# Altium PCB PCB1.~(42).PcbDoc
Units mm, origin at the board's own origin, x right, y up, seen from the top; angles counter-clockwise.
Board outline 145.29 x 144.91 mm, 2 copper layers (Top Layer, Bottom Layer); 41 components, 36 nets, 219 pads, 0 vias.
Unrouted connection lines stored in the file: 1.
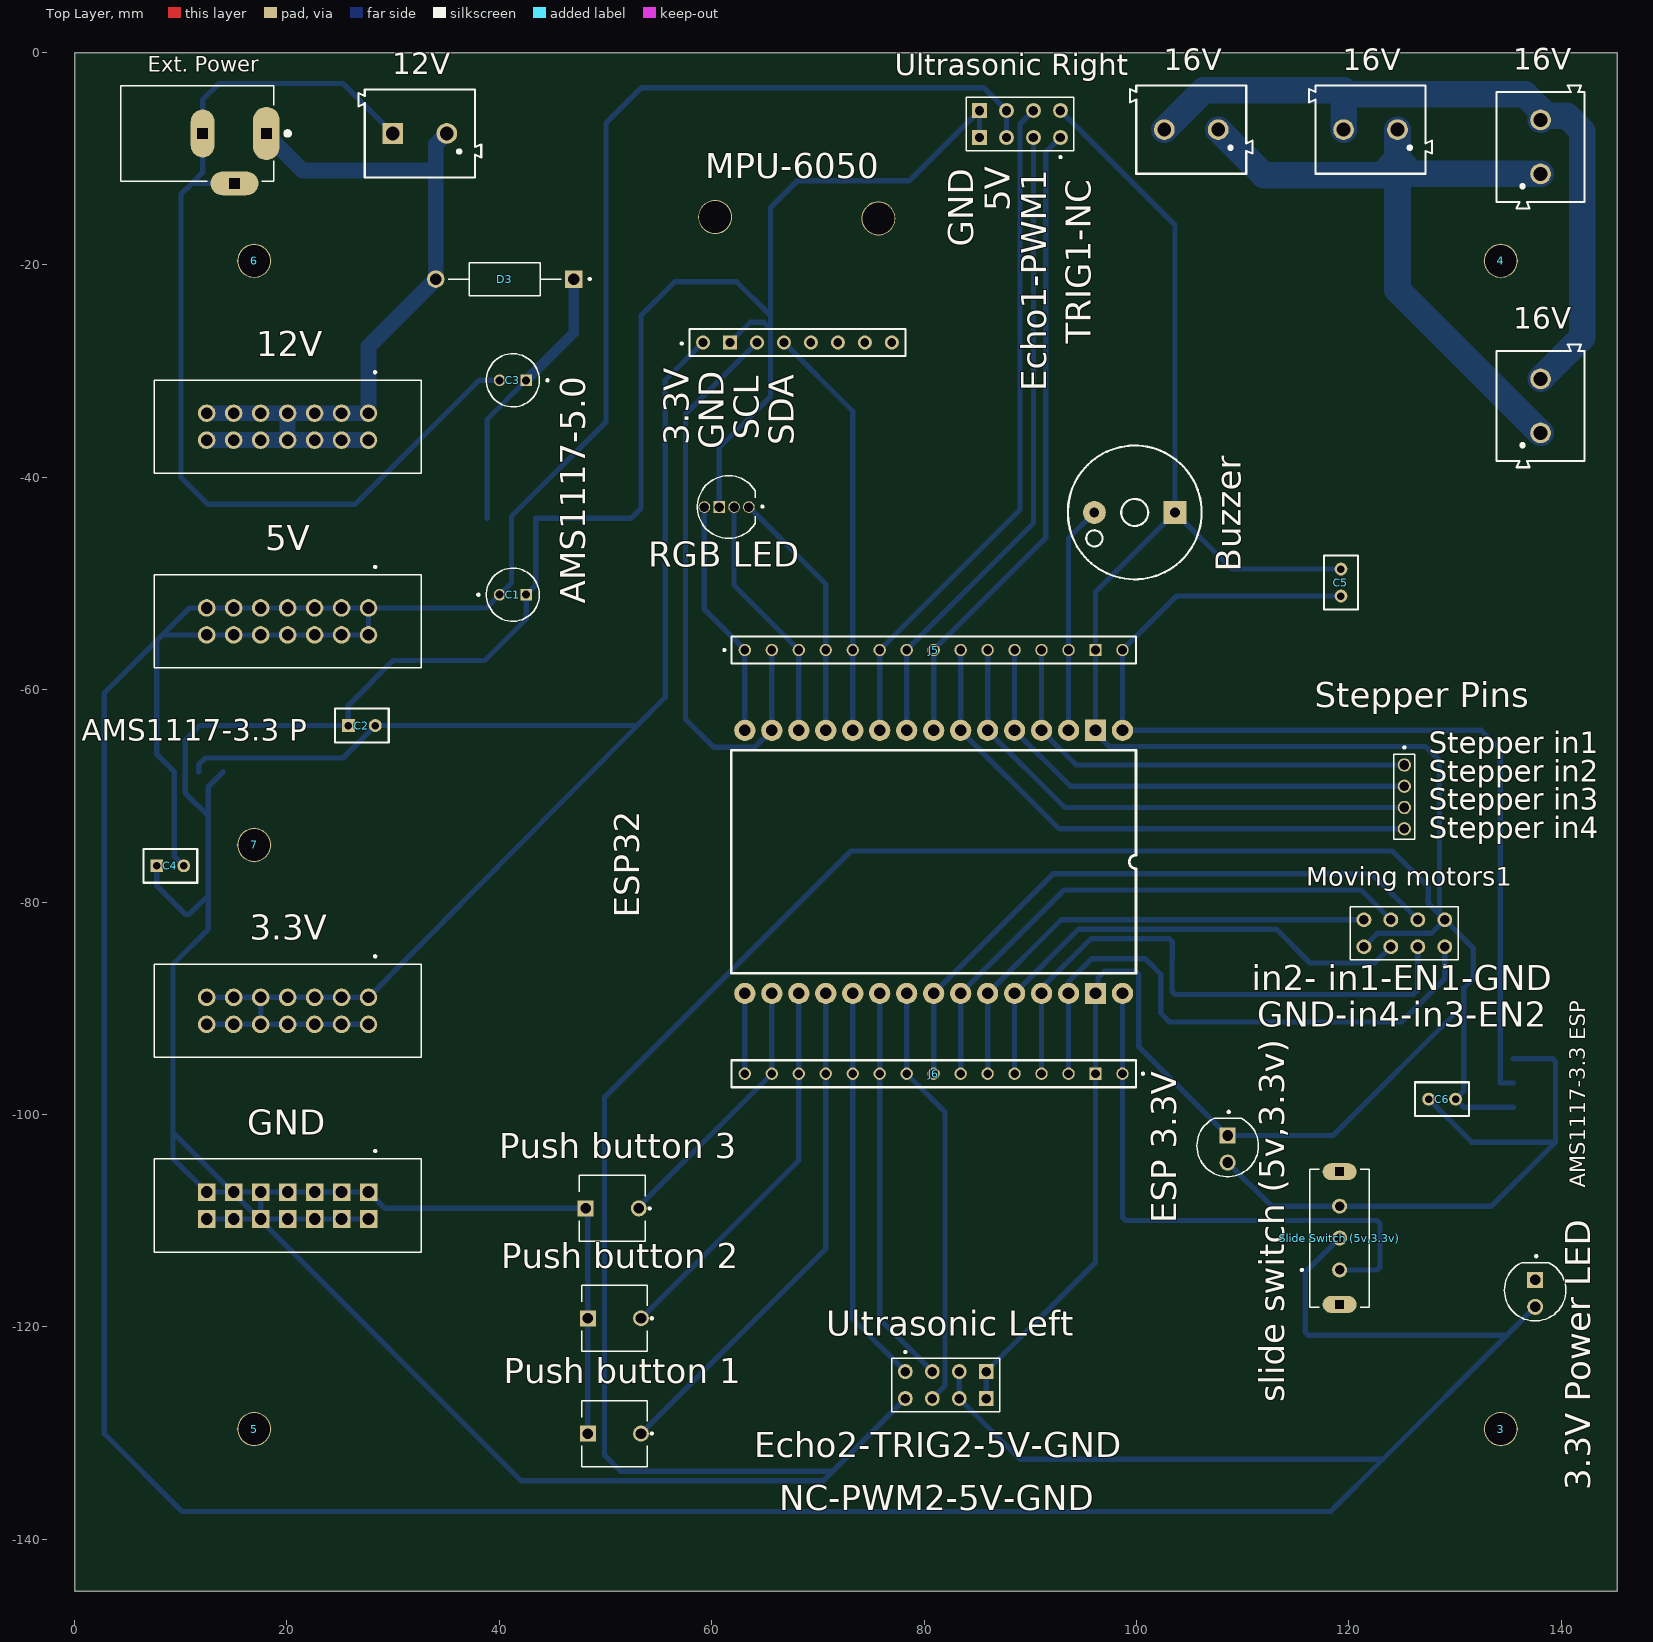
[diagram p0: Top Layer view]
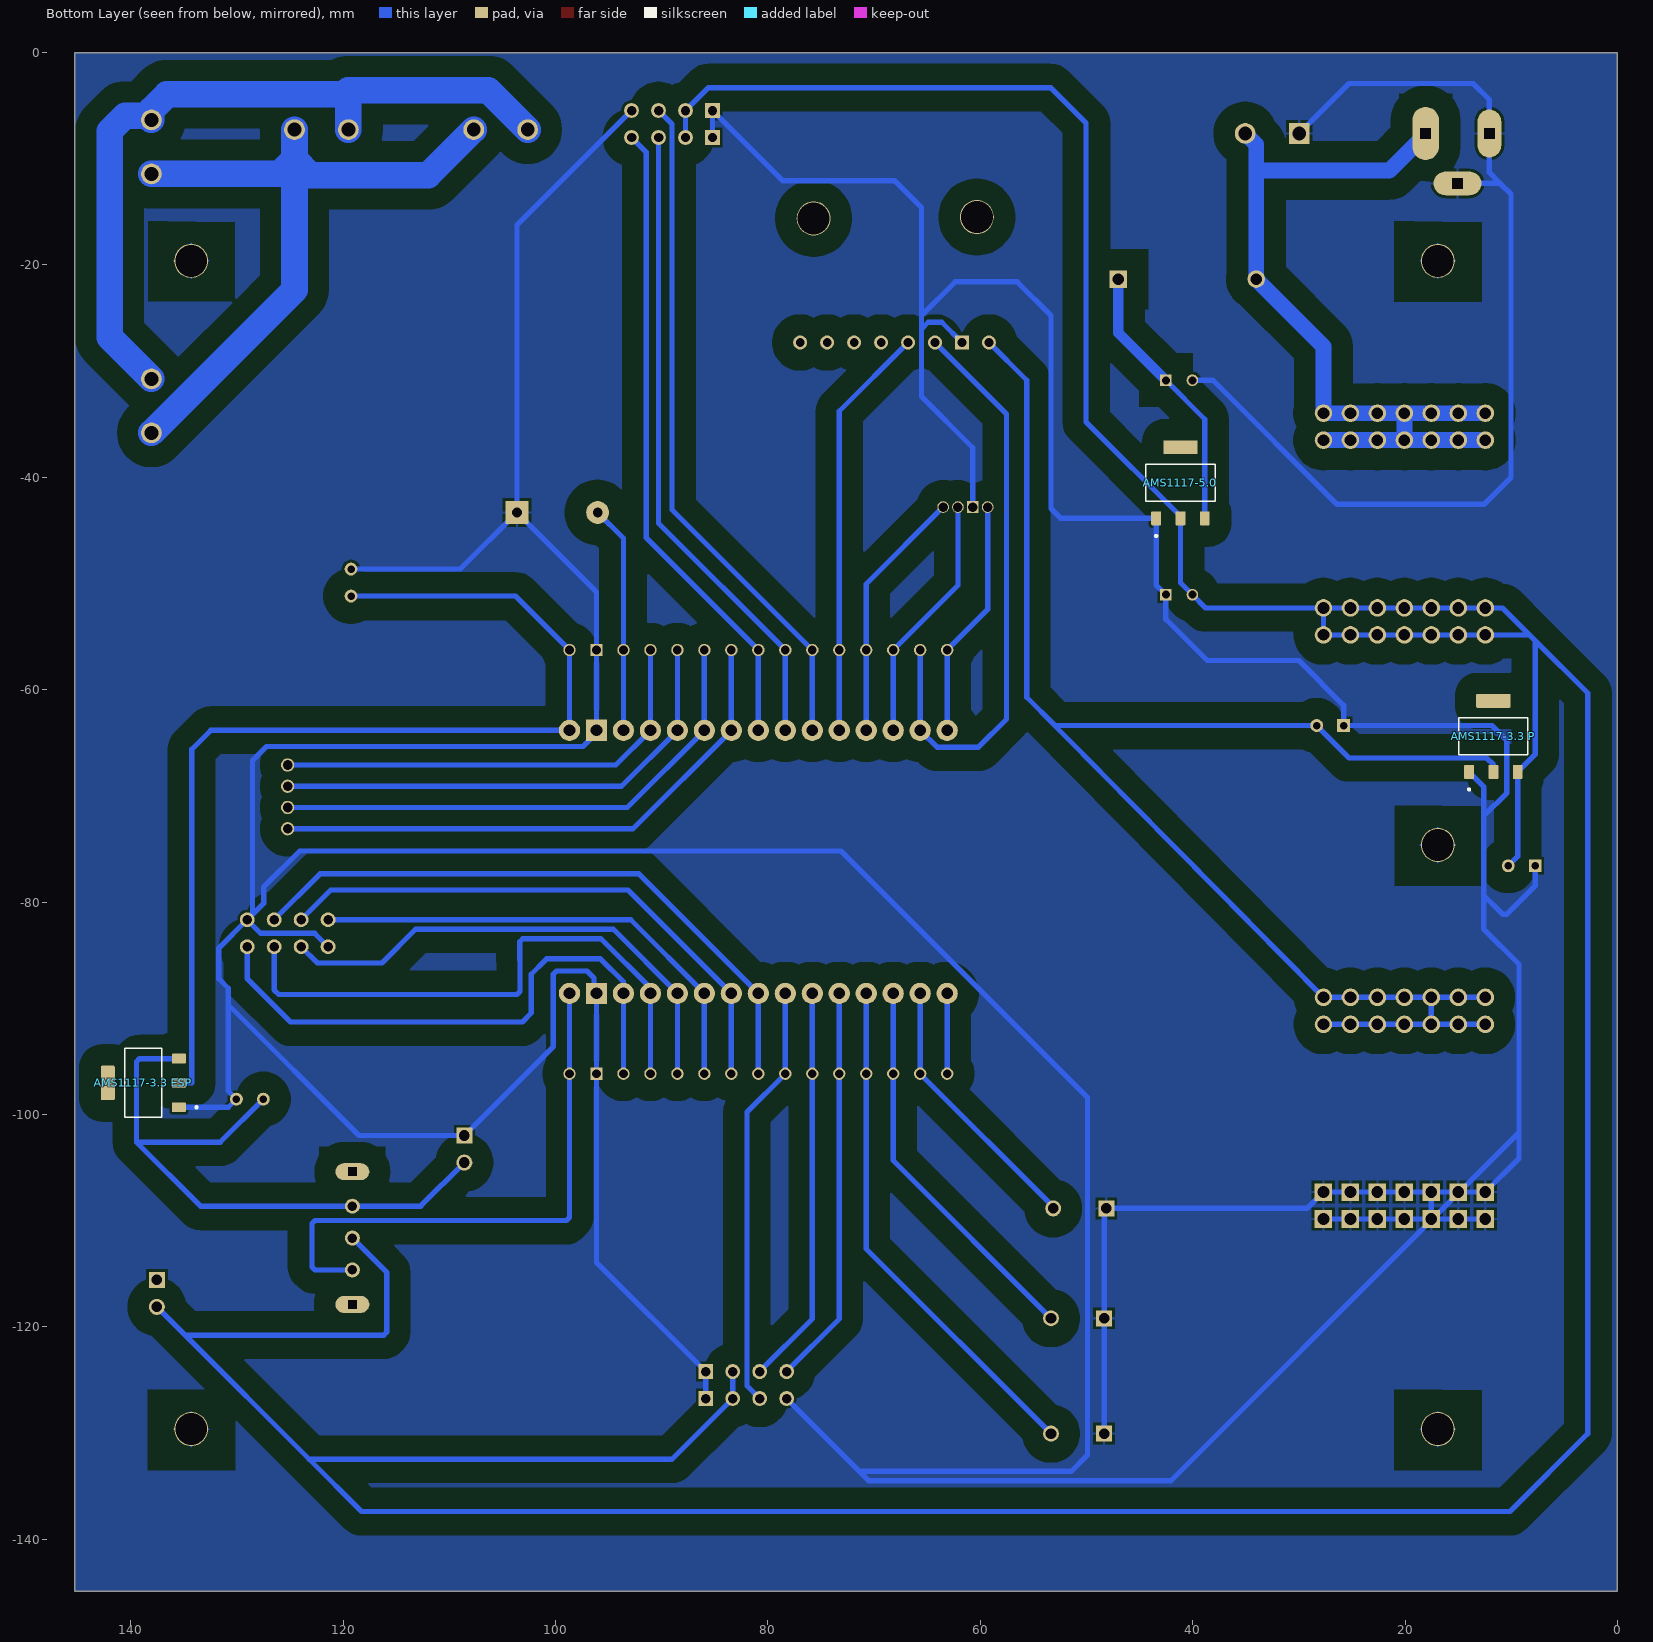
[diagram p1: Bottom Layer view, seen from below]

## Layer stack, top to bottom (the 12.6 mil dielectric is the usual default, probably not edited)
Top Solder: solder mask 0.0102, Solder Resist, Dk 3.5
Top Layer: signal copper 0.0356
Dielectric 1: dielectric 0.32, FR-4, Dk 4.8
Bottom Layer: signal copper 0.0356
Bottom Solder: solder mask 0.0102, Solder Resist, Dk 3.5

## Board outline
0,-144.907 145.288,-144.907 145.288,0 0,0

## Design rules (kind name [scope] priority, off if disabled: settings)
Clearance [All] p1: gap=0.254 ignorepadtopadclearanceinfootprint=FALSE except(0: Arc-Hole Track-Hole SMDPad-Hole THPad-Hole Via-Hole Fill-Hole Poly-Hole Region-Hole Text-Hole; 2: Arc-Poly Track-Poly SMDPad-Poly THPad-Poly)
PolygonConnect [All] p1: connectstyle=Relief reliefconductorwidth=0.254 reliefentries=4 polygonreliefangle="90 Angle" airgapwidth=0.254
RoutingLayers [All] p1: top layer_v5=FALSE bottom layer_v5=TRUE
RoutingVias [All] p1: holewidth=0.711 width=1.27 viastyle="Through Hole" minholewidth=0.711 minwidth=1.27 maxholewidth=0.711 maxwidth=1.27
SolderMaskExpansion [All] p1: expansion=0.102 istentingtop=FALSE
Width [All] p1: maxlimit=2.5 minlimit=0.254 preferedwidth=0.5
29 further rules are at their usual default settings.

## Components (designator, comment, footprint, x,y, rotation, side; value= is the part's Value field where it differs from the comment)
3 "Mounting Hole" PCBComponent_1 134.304,-129.619 r90 top
3.3V "3.3v pin headers block" AMPHENOL_52601-S14-4LF#1 20.066,-90.235 r180 top
"3.3V Power LED" "LED 5mm" "LED 5mm" 137.541,-116.84 r270 top
4 "Mounting Hole" PCBComponent_1 134.304,-19.619 r90 top
5 "Mounting Hole" PCBComponent_1 16.916,-129.619 r90 top
5V "5v pin headers block" AMPHENOL_52601-S14-4LF#1 20.066,-53.568 r180 top
6 "Mounting Hole" PCBComponent_1 16.916,-19.619 r90 top
7 "Mounting Hole" PCBComponent_1 16.916,-74.619 r90 top
12V "12v pin headers block" AMPHENOL_52601-S14-4LF#1 20.066,-35.235 r180 top
12V "From Buck" 691213510002#1 32.512,-7.62 r180 top
16V "From Buck" 691213510002#2 138.049,-8.89 r90 top
16V "From Buck" 691213510002#2 138.049,-33.274 r90 top
16V "From Buck" 691213510002#2 122.036,-7.26 r180 top
16V "From Buck" 691213510002#2 105.156,-7.26 r180 top
"AMS1117-3.3 ESP" "AMS1117-3.3" SOT229P700X180-4N 138.811,-97.028 r0 bottom
"AMS1117-3.3 P" "AMS1117-3.3" SOT229P700X180-4N 11.684,-64.389 r90 bottom
AMS1117-5.0 "AMS1117-5.0" SOT229P700X180-4N 41.148,-40.513 r90 bottom
Buzzer "Buzzer" "Buzzer 5V" 99.832,-43.307 r180 top
C1 "CAP  33UF 50V RADIAL" "CAP  33UF 50V RADIAL"#1 41.275,-51.054 r0 top
C2 "Ceramic Capacitor 100nF" C320C#1 34.051,-56.373 r0 top
C3 "CAP  33UF 50V RADIAL" "CAP  33UF 50V RADIAL"#2 41.275,-30.861 r180 top
C4 "Ceramic Capacitor 100nF" C320C#1 16.017,-69.581 r0 top
C5 "Ceramic Capacitor 100nF" C320C#2 126.253,-56.911 r270 top
C6 "Ceramic Capacitor 100nF" C320C#2 121.778,-105.552 r180 top
D3 "RL207" DIOAD1300W80L670D310 40.513,-21.336 r180 top
ESP32 "ESP32DEVKITV1" ESP32DEVKITV1 81.026,-75.508 r90 top
"ESP 3.3V" "LED 5mm" "LED 5mm" 108.585,-103.251 r270 top (schematic designator "Power ESP 3.3V")
"Ext. Power" "DC Power Jack Female Socket" "DC Power Jack Female Socket" 18.065,-7.62 r180 top
GND "GND pin headers block" AMPHENOL_52601-S14-4LF#2 20.066,-108.568 r180 top
J5 "TS-115-T-A-1" SAMTEC_TS-115-T-A-1#1 80.899,-56.261 r0 top
J6 "TS-115-T-A-1" SAMTEC_TS-115-T-A-1#2 80.899,-96.157 r180 top
"Moving motors1" "Pin header female block 8 pin" "Pin header female block 8 pin"#1 125.222,-82.931 r180 top
MPU-6050 "MPU-6050" MPU-6050 57.658,-28.829 r90 top
"Push button 1" "FSM8JRT" TE_FSM8JRT 53.34,-130.048 r180 top
"Push button 2" "FSM8JRT" TE_FSM8JRT 53.34,-119.189 r180 top
"Push button 3" "FSM8JRT" TE_FSM8JRT 53.137,-108.839 r180 top
"RGB LED" "common cathode" "LED RGB 5mm" 61.595,-42.799 r180 top
"Slide Switch (5v,3.3v)" "slide switch (5v,3.3v)" "Slide switch" 119.126,-111.633 r90 top
"Stepper Pins" "Pin hreader 4 pins" "Pin hreader 4 pins" 125.222,-67.088 r270 top
"Ultrasonic Left" "Pin header female block 8 pin" "Pin header female block 8 pin"#2 82.042,-125.476 r0 top
"Ultrasonic Right" "Pin header female block 8 pin" "Pin header female block 8 pin"#2 89.027,-6.731 r180 top

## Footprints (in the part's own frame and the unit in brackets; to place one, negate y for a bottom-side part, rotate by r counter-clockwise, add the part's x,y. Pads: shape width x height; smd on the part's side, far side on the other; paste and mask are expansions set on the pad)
691213510002#1 [mm]
  round 1.95 hole 1.3: 1(-2.54,0)
  rect 1.95x1.95 hole 1.3: 2(2.54,0)
  silkscreen extent -5.78,-4.15 5.78,4.15, body extent -5.68,-3.94 5.68,4.16, height 10
691213510002#2 [mm]
  round 1.95 hole 1.3: 1(-2.54,0) 2(2.54,0)
  silkscreen extent -5.78,-4.15 5.78,4.15, body extent -5.68,-3.94 5.68,4.16, height 10
AMPHENOL_52601-S14-4LF#1 [mm]
  round 1.65 hole 1.1: 1(-7.62,-1.27) 2(-7.62,1.27) 3(-5.08,-1.27) 4(-5.08,1.27) 5(-2.54,-1.27) 6(-2.54,1.27) 7(0,-1.27) 8(0,1.27) 9(2.54,-1.27) 10(2.54,1.27) 11(5.08,-1.27) 12(5.08,1.27) 13(7.62,-1.27) 14(7.62,1.27)
  silkscreen extent -12.57,-5.23 12.57,4.38, body extent -12.57,-4.38 12.57,4.38, height 9.53
AMPHENOL_52601-S14-4LF#2 [mm]
  rect 1.65x1.65 hole 1.1: 1(-7.62,-1.27) 2(-7.62,1.27) 3(-5.08,-1.27) 4(-5.08,1.27) 5(-2.54,-1.27) 6(-2.54,1.27) 7(0,-1.27) 8(0,1.27) 9(2.54,-1.27) 10(2.54,1.27) 11(5.08,-1.27) 12(5.08,1.27) 13(7.62,-1.27) 14(7.62,1.27)
  silkscreen extent -12.57,-5.23 12.57,4.38, body extent -12.57,-4.38 12.57,4.38, height 9.53
"Buzzer 5V" [mil]
  rect 85x85 hole 36: NEG(-149.61,0)
  round 85 hole 36: POS(149.61,0)
  silkscreen extent -248,-248 248,248, body extent -236,-236 236,236, height 394
C320C#1 [mm]
  rect 1.21x1.21 hole 0.71: 1(-8.27,-7)
  round 1.21 hole 0.71: 2(-5.73,-7)
  silkscreen extent -9.54,-8.59 -4.46,-5.41, body extent -9.53,-8.57 -4.45,-5.4, height 7.1
C320C#2 [mm]
  round 1.21 hole 0.71: 1(-8.27,-7) 2(-5.73,-7)
  silkscreen extent -9.54,-8.59 -4.46,-5.41, body extent -9.52,-8.57 -4.45,-5.4, height 7.1
"CAP  33UF 50V RADIAL"#1 [mm]
  rect 1.1x1.1 hole 0.75: N(1.25,0)
  round 1.1 hole 0.75: P(-1.25,0)
  silkscreen extent -3.35,-2.5 2.5,2.5, body extent -2.49,-2.5 2.5,2.5, height 11
"CAP  33UF 50V RADIAL"#2 [mm]
  round 1.1 hole 0.75: N(1.25,0)
  rect 1.1x1.1 hole 0.75: P(-1.25,0)
  silkscreen extent -3.35,-2.5 2.5,2.5, body extent -2.49,-2.5 2.5,2.5, height 11
"DC Power Jack Female Socket" [mm]
  oval 2.5x5 hole 1 square: 1(0,0)
  oval 2.25x4.5 hole 1 square: 2(6,0)
  oval 4.5x2.25 hole 1 square: 3(3,4.7)
  silkscreen extent -2.2,-4.5 13.7,4.5, body extent -0.7,-4.5 13.7,4.9, height 11
DIOAD1300W80L670D310 [mm]
  round 1.65 hole 1.1: A(6.5,0)
  rect 1.65x1.65 hole 1.1: C(-6.5,0)
  silkscreen extent -8.1,-1.55 5.32,1.55, body extent -6.9,-1.95 6.9,1.65, height 3.6
ESP32DEVKITV1 [mm]
  round 2 hole 1.1: 1(11.684,-17.653) 3(11.684,-12.573) 4(11.684,-10.033) 5(11.684,-7.493) 6(11.684,-4.953) 7(11.684,-2.413) 8(11.684,0.127) 9(11.684,2.667) 10(11.684,5.207) 11(11.684,7.747) 12(11.684,10.287) 13(11.684,12.827) 14(11.684,15.367) 15(11.684,17.907) 16(-13.086,17.907) 17(-13.086,15.367) 18(-13.086,12.827) 19(-13.086,10.287) 20(-13.086,7.747) 21(-13.086,5.207) 22(-13.086,2.667) 23(-13.086,0.127) 24(-13.086,-2.413) 25(-13.086,-4.953) 26(-13.086,-7.493) 27(-13.086,-10.033) 28(-13.086,-12.573) 30(-13.086,-17.653)
  rect 2x2 hole 1.1: 2(11.684,-15.113) 29(-13.086,-15.113)
  silkscreen extent -11.2,-18.92 9.79,19.18, body extent -15.13,-28.49 13.86,24.48, height 8.36
"LED 5mm" [mm]
  round 1.508 hole 1: A(1.27,0)
  rect 1.508x1.508 hole 1: C(-1.27,0)
  silkscreen extent -3.6,-2.9 2.6,2.9, body extent -2.88,-2.9 2.51,2.9, height 12.1
"LED RGB 5mm" [mm]
  round 1.1 hole 0.9: 1(-1.905,0) 2(-0.508,0) 4(2.286,0)
  rect 1.1x1.1 hole 0.9: 3(0.889,0)
  silkscreen extent -3.27,-2.95 2.95,2.95, body extent -2.47,-3.05 2.98,2.84, height 9.6
MPU-6050 [mil]
  round 52 hole 32: 01(60,-60) 03(60,-260) 04(60,-360) 05(60,-460) 06(60,-560) 07(60,-660) 08(60,-760)
  rect 52x52 hole 32: 02(60,-160)
  round 125.98 hole 118.11: ""(520,-710) ""(525,-105)
  silkscreen extent 10,-810 110,23, body extent 15,-811 615,-9, height 612
PCBComponent_1 [mm]
  round 3.2 hole 3: ""(0,0)
  Bottom Layer lines w0.15: 0,1.649 0,-1.651 ; -1.651,0 1.649,0
"Pin header female block 8 pin"#1 [mm]
  round 1.398 hole 0.89: 1(-3.81,1.27) 2(-1.27,1.27) 3(1.27,1.27) 4(3.81,1.27) 5(-3.81,-1.27) 6(-1.27,-1.27) 7(1.27,-1.27) 8(3.81,-1.27)
  silkscreen extent -5.08,-2.52 5.08,3.21, body extent -5.08,-2.51 5.08,2.51, height 6.22
"Pin header female block 8 pin"#2 [mm]
  round 1.398 hole 0.89: 1(-3.81,1.27) 2(-1.27,1.27) 3(1.27,1.27) 5(-3.81,-1.27) 6(-1.27,-1.27) 7(1.27,-1.27)
  rect 1.398x1.398 hole 0.89: 4(3.81,1.27) 8(3.81,-1.27)
  silkscreen extent -5.08,-2.52 5.08,3.21, body extent -5.08,-2.51 5.08,2.51, height 6.22
"Pin hreader 4 pins" [mm]
  round 1.25 hole 0.9: 1(0,0) 2(2,0) 3(4,0) 4(6,0)
  silkscreen extent -1.75,-1 7,1, body extent -1.01,-1.02 6.98,0.98, height 5.78
SAMTEC_TS-115-T-A-1#1 [mil]
  round 45.78 hole 32: 01(-700,0) 02(-600,0) 03(-500,0) 04(-400,0) 05(-300,0) 06(-200,0) 07(-100,0) 08(0,0) 09(100,0) 10(200,0) 11(300,0) 12(400,0) 13(500,0) 15(700,0)
  rect 45.78x45.78 hole 32: 14(600,0)
  silkscreen extent -780,-50 750,50, body extent -754,-50 754,50, height 326
SAMTEC_TS-115-T-A-1#2 [mil]
  round 45.78 hole 32: 01(-700,0) 03(-500,0) 04(-400,0) 05(-300,0) 06(-200,0) 07(-100,0) 08(0,0) 09(100,0) 10(200,0) 11(300,0) 12(400,0) 13(500,0) 14(600,0) 15(700,0)
  rect 45.78x45.78 hole 32: 02(-600,0)
  silkscreen extent -780,-50 750,50, body extent -754,-50 754,50, height 326
"Slide switch" [mm]
  round 1.408 hole 0.9: 1(-3,0) 2(0,0) 3(3,0)
  oval 1.6x3.2 hole 0.8 square: SH1(-6.25,0) SH2(6.25,0)
  silkscreen extent -6.5,-2.8 6.5,3.66, body extent -6.5,-5.8 6.5,2.8, height 6
SOT229P700X180-4N [mm]
  rrect15% 1.31x0.93 smd: 1(-3.345,2.29) 2(-3.345,0) 3(-3.345,-2.29)
  rrect15% 1.31x3.24 smd: 4(3.345,0)
  silkscreen extent -5.1,-3.25 1.75,3.25, body extent -3.5,-3.25 3.5,3.25, height 1.8
TE_FSM8JRT [mil]
  round 59 hole 39: 1(0,0)
  rect 59x59 hole 39: 2(197,0)
  silkscreen extent -44,-122 221,122, body extent -22,-122 222,122, height 372

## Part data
3.3V 5V 12V GND: library part 52601-S14-4LF, Package=None
"3.3V Power LED" "ESP 3.3V": "Red 623nm LED Indication - Discrete 1.9V Radial", Package=None
12V 16V 16V 16V 16V: library part "Terminal Block", "2 Position Wire to Board Terminal Block Horizontal with Board 0.200 (5.08mm) Through Hole", Package=None
"AMS1117-3.3 ESP" "AMS1117-3.3 P" AMS1117-5.0 J5 J6 "Moving motors1" "Stepper Pins" "Ultrasonic Left" "Ultrasonic Right": Package=None
Buzzer: library part "Buzzer 5V", "BUZZER 2.3KHZ 4-6VDC", Package=None
C1 C3: "NHG-A", Package=None
C2 C4 C5 C6: "0.1ÂµF Â±20% 50V Ceramic Capacitor Z5U Radial", Package="Radial KEMET"
D3: "Semiconductors and Actives, Power Diodes, Discretes (diodes, transistors, thyristors ...), Diodes", Package=None
"Ext. Power": "2.0 mm Center Pin, 2.5 A, Right Angle, Through Hole, Dc Power Jack Connector", Package=None
"Push button 1" "Push button 2" "Push button 3": "Tactile Switches PUSHBUTTON SWITCH TACT", Package=None
"RGB LED": library part "LED RGB 5mm", Package=None
"Slide Switch (5v,3.3v)": library part "Slide switch", Package=None

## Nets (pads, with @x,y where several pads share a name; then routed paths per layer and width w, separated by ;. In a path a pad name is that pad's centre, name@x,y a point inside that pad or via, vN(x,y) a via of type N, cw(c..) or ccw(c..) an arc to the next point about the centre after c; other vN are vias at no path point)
3.3V: 3.3V.1 3.3V.2 3.3V.3 3.3V.4 3.3V.5 3.3V.6 3.3V.7 3.3V.8 3.3V.9 3.3V.10 3.3V.11 3.3V.12 3.3V.13 3.3V.14 "AMS1117-3.3 P.2" C2.2 MPU-6050.01 | length 154.9
  Bottom Layer w0.5: 11.684,-67.734 11.684,-67.056 12.319,-66.421 25.273,-66.421 C2.2 52.959,-63.373 55.626,-60.706 ; 3.3V.14 3.3V.12 3.3V.10 ; 3.3V.13 3.3V.11 3.3V.9 ; 3.3V.2 3.3V.4 3.3V.6 3.3V.8 3.3V.10 ; MPU-6050.01 55.626,-30.861 55.626,-60.706 ; 3.3V.10 3.3V.9 ; 3.3V.9 3.3V.7 3.3V.5 3.3V.3 3.3V.1 55.626,-60.706
+5: 5V.1 5V.2 5V.3 5V.4 5V.5 5V.6 5V.7 5V.8 5V.9 5V.10 5V.11 5V.12 5V.13 5V.14 "3.3V Power LED.A" "AMS1117-3.3 P.3" "Slide Switch (5v,3.3v).2" "Ultrasonic Left.3" "Ultrasonic Left.7" "Ultrasonic Right.3" "Ultrasonic Right.7" AMS1117-5.0.2 C1.P C4.2 | length 466
  Bottom Layer w0.5: C4.2 9.394,-75.688 9.394,-67.734 7.747,-66.087 7.747,-55.372 ; 83.312,-124.206 83.312,-126.746 89.027,-132.461 123.19,-132.461 ; 87.757,-8.001 87.757,-5.461 85.598,-3.302 53.373,-3.302 50.038,-6.637 50.038,-34.778 41.148,-43.668 AMS1117-5.0.2 41.148,-49.931 C1.P 38.781,-52.298 5V.1 ; 119.126,-111.633 115.875,-114.884 115.875,-120.484 116.168,-120.777 134.874,-120.777 ; 137.541,-118.11 134.874,-120.777 ; 7.747,-55.372 8.281,-54.838 ; 7.747,-55.372 2.794,-60.325 2.794,-130.048 10.125,-137.379 118.272,-137.379 123.19,-132.461 ; 8.281,-54.838 5V.12 5V.10 5V.8 5V.6 5V.4 5V.2 5V.1 ; 8.281,-54.838 10.821,-52.298 5V.13 5V.11 5V.9 5V.7 5V.5 5V.3 5V.1 ; 123.19,-132.461 134.874,-120.777
+12: 12V.1 12V.2@27.686,-36.505 12V.3 12V.4 12V.5 12V.6 12V.7 12V.8 12V.9 12V.10 12V.11 12V.12 12V.13 12V.14 "Ext. Power.1" D3.A | length 79.9
  Bottom Layer w0.5: 18.065,-7.696 18.065,-7.62
  Bottom Layer w1.5: 12V.14 12V.12 12V.10 12V.8 ; 12V.13 12V.11 12V.9 12V.7 ; 18.065,-7.696 21.489,-11.12 33.965,-11.12 34.013,-11.072 ; 12V.2@27.686,-36.505 12V.4 12V.6 12V.8 ; 12V.1@35.052,-7.62 34.013,-8.659 34.013,-11.072 ; 12V.8 12V.7 ; 12V.7 12V.5 12V.3 27.686,-33.965 27.686,-27.663 D3.A 34.013,-11.072
GND: 12V.2@29.972,-7.62 "3.3V Power LED.C" "AMS1117-3.3 ESP.1" "AMS1117-3.3 P.1" "ESP 3.3V.C" "Ext. Power.2" "Ext. Power.3" "Moving motors1.4" "Moving motors1.5" "Push button 1.2" "Push button 2.2" "Push button 3.2" "RGB LED.3" "Ultrasonic Left.4" "Ultrasonic Left.5" "Ultrasonic Left.8" "Ultrasonic Right.4" "Ultrasonic Right.5" "Ultrasonic Right.8" AMS1117-5.0.1 Buzzer.NEG C1.N C2.1 C3.N C4.1 C5.1 C6.1 ESP32.2 ESP32.29 GND.1 GND.2 GND.3 GND.4 GND.5 GND.6 GND.7 GND.8 GND.9 GND.10 GND.11 GND.12 GND.13 GND.14 J5.14 J6.02 MPU-6050.02 | length 876.9
  Bottom Layer w0.5: C4.1 7.747,-78.486 10.397,-81.136 10.812,-81.136 12.598,-79.35 ; 9.271,-101.702 GND.11@14.868,-107.298 ; GND.14 GND.12 GND.10@17.408,-109.838 ; 13.974,-67.734 12.598,-69.11 12.598,-71.907 ; 15.065,-12.32 11.048,-12.32 ; GND.2 GND.4 GND.6 GND.8 GND.10 ; 12V.2@29.972,-7.62 25.273,-2.921 13.589,-2.921 12.065,-4.445 12.065,-7.62 12.065,-11.303 11.048,-12.32 ; C3.N 38.1,-30.861 26.416,-42.545 12.573,-42.545 10.033,-40.005 10.033,-13.335 11.048,-12.32 ; 48.336,-130.048 48.336,-119.189 48.336,-109.042 48.133,-108.839 29.227,-108.839 GND.1 GND.3 GND.5 GND.7 GND.9 ; 60.706,-42.799 60.706,-37.211 65.532,-32.385 65.532,-26.035 ; MPU-6050.02 63.627,-25.4 64.897,-25.4 65.532,-26.035 ; 78.232,-126.746 71.374,-133.604 ; 85.217,-8.001 85.217,-5.461 78.613,-12.065 68.072,-12.065 65.532,-14.605 65.532,-24.765 ; 85.852,-126.746 85.852,-124.206 96.139,-113.919 J6.02 ESP32.29 96.378,-88.355 96.378,-87.137 97.028,-86.487 99.91,-86.487 100.203,-86.78 100.203,-93.599 108.585,-101.981 118.491,-101.981 130.81,-89.662 ; 92.837,-5.461 103.632,-16.256 Buzzer.NEG ; C5.1 108.966,-48.641 Buzzer.NEG ; 121.412,-84.201 122.682,-82.931 127.762,-82.931 129.032,-81.661 ; 135.466,-99.318 130.814,-99.318 C6.1 130.81,-97.79 130.81,-89.662 ; 12.598,-79.35 12.598,-71.907 ; 12.598,-79.35 12.598,-82.529 9.276,-85.851 9.276,-101.702 9.276,-104.128 GND.13 GND.11@14.868,-107.298 ; 12.598,-71.907 10.414,-69.723 10.414,-64.77 11.811,-63.373 C2.1 25.781,-61.468 29.995,-57.254 38.631,-57.254 42.525,-53.36 C1.N 43.438,-50.141 AMS1117-5.0.1 52.408,-43.858 53.34,-42.926 53.34,-24.765 56.515,-21.59 62.357,-21.59 65.532,-24.765 ; GND.11@14.868,-107.298 GND.11 GND.9 ; GND.11@14.868,-107.298 GND.10@17.408,-109.838 ; GND.10@17.408,-109.838 42.062,-134.493 70.485,-134.493 71.374,-133.604 ; GND.10@17.408,-109.838 GND.10 ; GND.10 GND.9 ; 65.532,-26.035 65.532,-24.765 ; 71.374,-133.604 51.435,-133.604 49.911,-132.08 49.911,-98.4 73.127,-75.184 124.079,-75.184 127.483,-78.588 127.483,-80.112 128.524,-81.153 ; Buzzer.NEG 96.139,-50.8 J5.14 ESP32.2 96.139,-64.084 97.409,-65.354 127.203,-65.354 128.524,-66.675 128.524,-81.153 ; 128.524,-81.153 129.032,-81.661 ; 129.032,-81.661 131.699,-84.328 131.699,-87.217 130.81,-88.106 130.81,-89.662
Net16V_1: 16V.1 | length 67.5
  Bottom Layer w2.5: 16V.1@107.696,-7.26 111.993,-11.557 123.063,-11.557 124.576,-10.044 124.576,-22.341 16V.1@138.049,-35.814 ; 16V.1@124.576,-7.26 124.576,-10.022 125.984,-11.43 16V.1@138.049,-11.43
Net16V_2: 16V.2 | length 71.9
  Bottom Layer w2.5: 16V.2@102.616,-7.26 106.32,-3.556 119.496,-3.556 16V.2@119.496,-7.26 ; 119.496,-3.937 136.585,-3.937 138.049,-5.401 138.049,-6.35 138.45,-5.949 140.522,-5.949 141.986,-7.413 141.986,-26.797 16V.2@138.049,-30.734
"NetAMS1117-3.3 ESP_2": "AMS1117-3.3 ESP.2" C5.2 ESP32.1 J5.15 | length 99.2
  Bottom Layer w0.5: C5.2 103.759,-51.181 J5.15 ESP32.1 132.461,-63.824 134.239,-65.602 134.239,-97.028 135.466,-97.028
"NetAMS1117-3.3 ESP_3": "AMS1117-3.3 ESP.3" "ESP 3.3V.A" "Slide Switch (5v,3.3v).3" C6.2 | length 60.4
  Bottom Layer w0.5: 108.585,-104.521 112.697,-108.633 119.126,-108.633 133.429,-108.633 139.446,-102.616 ; C6.2 131.572,-102.616 139.446,-102.616 ; 135.466,-94.738 139.153,-94.738 139.446,-95.031 139.446,-102.616
NetAMS1117-5.0_3: AMS1117-5.0.3 C3.P D3.C | length 25.9
  Bottom Layer w0.5: AMS1117-5.0.3 38.858,-34.528 C3.P
  Bottom Layer w1: C3.P 47.013,-26.373 D3.C
NetBuzzer_POS: Buzzer.POS ESP32.3 J5.13 | length 21.5
  Bottom Layer w0.5: ESP32.3 J5.13 93.599,-45.74 Buzzer.POS
NetESP32_4: "Stepper Pins.1" ESP32.4 J5.12 | length 43.1
  Bottom Layer w0.5: J5.12 ESP32.4 94.323,-67.088 125.222,-67.088
NetESP32_5: "Stepper Pins.2" ESP32.5 J5.11 | length 46.4
  Bottom Layer w0.5: J5.11 ESP32.5 93.783,-69.088 125.222,-69.088
NetESP32_6: "Stepper Pins.3" ESP32.6 J5.10 | length 49.8
  Bottom Layer w0.5: J5.10 ESP32.6 93.243,-71.088 125.222,-71.088
NetESP32_7: "Stepper Pins.4" ESP32.7 J5.09 | length 53.2
  Bottom Layer w0.5: J5.09 ESP32.7 92.703,-73.088 125.222,-73.088
NetESP32_8: "Ultrasonic Right.1" ESP32.8 J5.08 | length 60.8
  Bottom Layer w0.5: ESP32.8 J5.08 91.44,-45.72 91.44,-9.398 92.837,-8.001
NetESP32_9: "Ultrasonic Right.2" ESP32.9 J5.07 | length 60.8
  Bottom Layer w0.5: ESP32.9 J5.07 90.297,-44.323 90.297,-8.001
NetESP32_10: "Ultrasonic Right.6" ESP32.10 J5.06 | length 64.4
  Bottom Layer w0.5: ESP32.10 J5.06 89.027,-43.053 89.027,-6.731 90.297,-5.461
NetESP32_11: ESP32.11 J5.05 MPU-6050.04 | length 39.2
  Bottom Layer w0.5: MPU-6050.04 73.279,-33.782 J5.05 ESP32.11
NetESP32_12: "RGB LED.1" ESP32.12 J5.04 | length 24
  Bottom Layer w0.5: 63.5,-42.799 70.739,-50.038 J5.04 ESP32.12
NetESP32_13: "RGB LED.2" ESP32.13 J5.03 | length 23.6
  Bottom Layer w0.5: 62.103,-42.799 62.103,-50.165 J5.03 ESP32.13
NetESP32_14: ESP32.14 J5.02 MPU-6050.03 | length 55.7
  Bottom Layer w0.5: MPU-6050.03 57.531,-34.036 57.531,-62.777 60.159,-65.405 64.078,-65.405 ESP32.14 J5.02
NetESP32_15: "RGB LED.4" ESP32.15 J5.01 | length 22.6
  Bottom Layer w0.5: 59.309,-42.799 59.309,-52.451 J5.01 ESP32.15
NetESP32_16: ESP32.16 J6.15 | length 7.6
  Bottom Layer w0.5: J6.15 ESP32.16
NetESP32_17: "Push button 3.1" ESP32.17 J6.14 | length 25.4
  Bottom Layer w0.5: 53.137,-108.839 53.137,-108.679 J6.14 ESP32.17
NetESP32_18: "Push button 2.1" ESP32.18 J6.13 | length 36.8
  Bottom Layer w0.5: 53.34,-119.189 68.199,-104.33 J6.13 ESP32.18
NetESP32_19: "Push button 1.1" ESP32.19 J6.12 | length 48.7
  Bottom Layer w0.5: 53.34,-130.048 70.739,-112.649 J6.12 ESP32.19
NetESP32_20: "Ultrasonic Left.1" ESP32.20 J6.11 | length 37.7
  Bottom Layer w0.5: ESP32.20 J6.11 73.279,-119.253 78.232,-124.206
NetESP32_21: "Ultrasonic Left.2" ESP32.21 J6.10 | length 37.7
  Bottom Layer w0.5: ESP32.21 J6.10 75.819,-119.253 80.772,-124.206
NetESP32_22: "Ultrasonic Left.6" ESP32.22 J6.09 | length 40.1
  Bottom Layer w0.5: ESP32.22 J6.09 81.975,-99.773 81.975,-125.543 80.772,-126.746
NetESP32_23: "Moving motors1.6" ESP32.23 J6.08 | length 59.6
  Bottom Layer w0.5: J6.08 ESP32.23 92.15,-77.343 122.174,-77.343 126.492,-81.661
NetESP32_24: "Moving motors1.7" ESP32.24 J6.07 | length 53.3
  Bottom Layer w0.5: J6.07 ESP32.24 93.166,-78.867 121.158,-78.867 123.952,-81.661
NetESP32_25: "Moving motors1.8" ESP32.25 J6.06 | length 45.9
  Bottom Layer w0.5: J6.06 ESP32.25 92.912,-81.661 121.412,-81.661
NetESP32_26: "Moving motors1.3" ESP32.26 J6.05 | length 47.4
  Bottom Layer w0.5: J6.05 ESP32.26 94.563,-82.55 113.157,-82.55 116.332,-85.725 122.428,-85.725 123.952,-84.201
NetESP32_27: "Moving motors1.2" ESP32.27 J6.04 | length 54.6
  Bottom Layer w0.5: J6.04 ESP32.27 91.059,-88.102 95.71,-83.451 103.085,-83.451 103.378,-83.744 103.378,-85.432 103.339,-85.471 103.339,-88.402 103.632,-88.695 126.062,-88.695 126.492,-88.265 126.492,-84.201
NetESP32_28: "Moving motors1.1" ESP32.28 J6.03 | length 54.3
  Bottom Layer w0.5: J6.03 ESP32.28 93.599,-87.503 95.758,-85.344 100.838,-85.344 100.984,-85.49 102.286,-86.792 102.286,-90.449 103.124,-91.288 124.943,-91.288 129.032,-87.198 129.032,-84.201
NetESP32_30: "Slide Switch (5v,3.3v).1" ESP32.30 J6.01 | length 53.6
  Bottom Layer w0.5: ESP32.30 J6.01 98.679,-109.689 98.972,-109.982 122.643,-109.982 122.936,-110.275 122.936,-114.34 122.643,-114.633 119.126,-114.633
pads on no net: 3. 4. 5. 6. 7. "AMS1117-3.3 ESP.4" "AMS1117-3.3 P.4" "Slide Switch (5v,3.3v).SH1" "Slide Switch (5v,3.3v).SH2" AMS1117-5.0.4 MPU-6050. MPU-6050.05 MPU-6050.06 MPU-6050.07 MPU-6050.08

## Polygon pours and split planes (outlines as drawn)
GND on Bottom Layer "GND_L02_P000" (solid, pour order 0): 0,-144.907 145.288,-144.907 145.288,0 0,0

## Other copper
Bottom Layer:
  pour cut-out: 130.152,-125.984 138.407,-125.857 138.407,-133.486 130.152,-133.486
  pour cut-out: 130.152,-15.984 138.407,-15.857 138.407,-23.486 130.152,-23.486
  pour cut-out: 12.763,-15.984 21.018,-15.857 21.018,-23.486 12.763,-23.486
  pour cut-out: 12.763,-125.984 21.018,-125.857 21.018,-133.486 12.763,-133.486
  pour cut-out: 12.763,-70.984 21.018,-70.857 21.018,-78.486 12.763,-78.486

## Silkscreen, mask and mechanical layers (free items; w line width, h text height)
Top Overlay:
  text "5V" at 88.851,-14.93 h4 r90
  text "GND" at 85.428,-18.299 h4 r90
  text "TRIG1-NC" at 96.471,-27.403 h4 r90
  text "Echo1-PWM1" at 92.286,-31.877 h4 r90
  text "SCL" at 65.235,-36.446 h4 r90
  text "3.3V" at 58.631,-36.957 h4 r90
  text "SDA" at 68.537,-36.973 h4 r90
  text "GND" at 61.933,-37.343 h4 r90
  text "Stepper in1" at 127.508,-66.688 h3.5
  text "Stepper in2" at 127.508,-69.355 h3.5
  text "Stepper in3" at 127.508,-72.022 h3.5
  text "Stepper in4" at 127.508,-74.689 h3.5
  text "in2- in1-EN1-GND" at 110.871,-89.111 h4
  text "GND-in4-in3-EN2" at 111.379,-92.54 h4
  text "Echo2-TRIG2-5V-GND" at 63.991,-133.053 h4
  text "NC-PWM2-5V-GND" at 66.376,-138.049 h4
